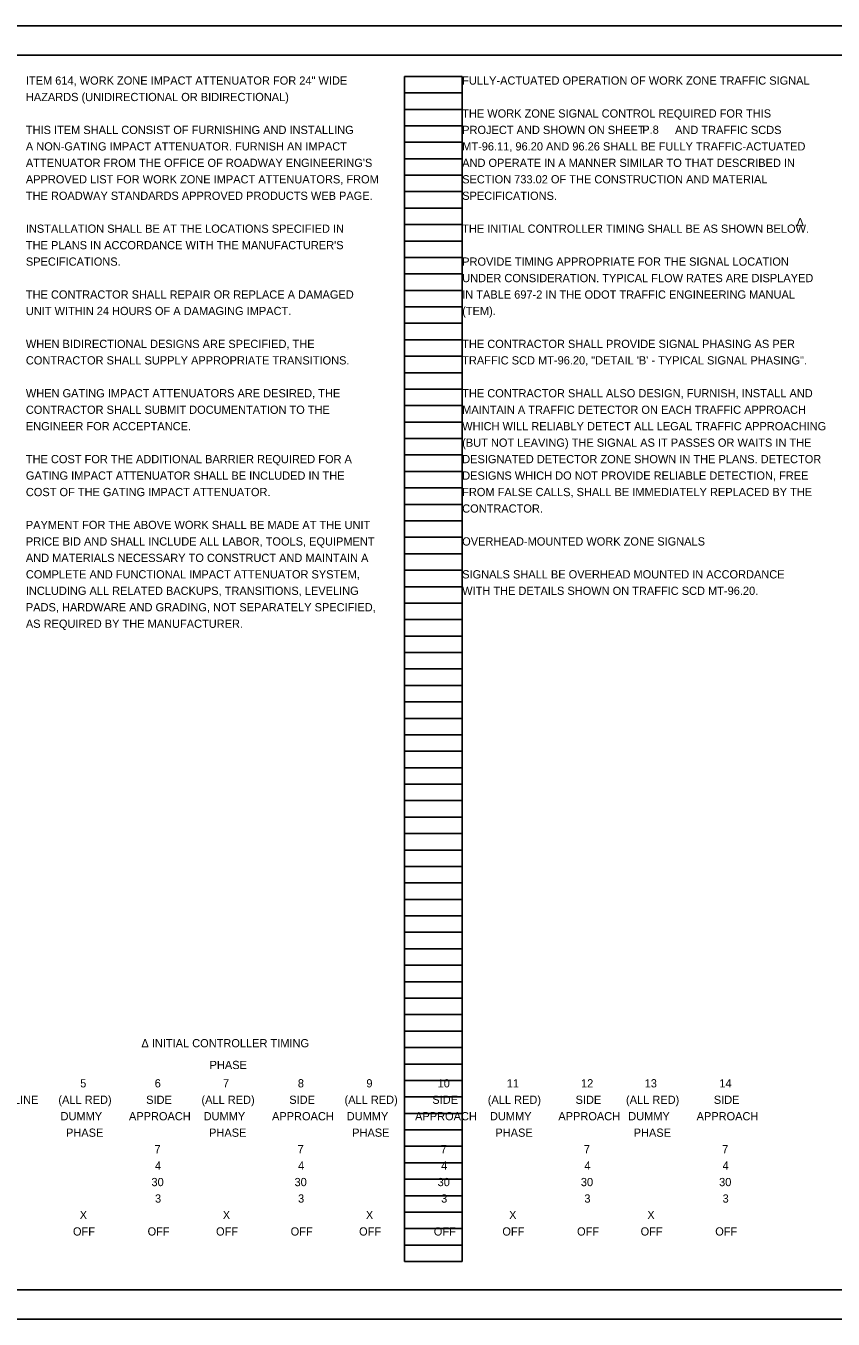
# Model space of a CAD drawing. Extents: x 0 to 40, y 0 to 22.
# Drawn here: x 9.82 to 23.55, y 0 to 22 of the extents above; entities that cross this region are included whole.
import ezdxf

# ---------------------------------------------------------------- set-up
doc = ezdxf.new("R2010")
doc.units = 0
for name, color, linetype in [('SH_Border', 7, 'Continuous'), ('SH_Cut_Line', 7, 'Continuous'), ('SH_Data', 7, 'Continuous'), ('SH_Text', 7, 'Continuous')]:
    doc.layers.add(name, color=color, linetype=linetype)

msp = doc.modelspace()

# ---------------------------------------------------------------- linework, layer by layer
at = {"layer": 'SH_Border'}
msp.add_lwpolyline([(1.5, 21.5), (33.5, 21.5), (33.5, 0.5), (1.5, 0.5)], close=True, dxfattribs=at)
at = {"layer": 'SH_Cut_Line'}
msp.add_lwpolyline([(0, 0), (34, 0), (34, 22), (0, 22)], close=True, dxfattribs=at)
at = {"layer": 'SH_Data'}
for p, q in [((16.26, 0.98), (16.26, 21.14)), ((16.26, 21.14), (17.24, 21.14)), ((17.24, 0.98), (17.24, 21.14)), ((16.26, 20.86), (17.24, 20.86)), ((16.26, 20.58), (17.24, 20.58)), ((16.26, 20.3), (17.24, 20.3)), ((16.26, 20.02), (17.24, 20.02)), ((16.26, 19.74), (17.24, 19.74)), ((16.26, 19.46), (17.24, 19.46)), ((16.26, 19.18), (17.24, 19.18)), ((16.26, 18.9), (17.24, 18.9)), ((16.26, 18.62), (17.24, 18.62)), ((16.26, 18.34), (17.24, 18.34)), ((16.26, 18.06), (17.24, 18.06)), ((16.26, 17.78), (17.24, 17.78)), ((16.26, 17.5), (17.24, 17.5)), ((16.26, 17.22), (17.24, 17.22)), ((16.26, 16.94), (17.24, 16.94)), ((16.26, 16.66), (17.24, 16.66)), ((16.26, 16.38), (17.24, 16.38)), ((16.26, 16.1), (17.24, 16.1)), ((16.26, 15.82), (17.24, 15.82)), ((16.26, 15.54), (17.24, 15.54)), ((16.26, 15.26), (17.24, 15.26)), ((16.26, 14.98), (17.24, 14.98)), ((16.26, 14.7), (17.24, 14.7)), ((16.26, 14.42), (17.24, 14.42)), ((16.26, 14.14), (17.24, 14.14)), ((16.26, 13.86), (17.24, 13.86)), ((16.26, 13.58), (17.24, 13.58)), ((16.26, 13.3), (17.24, 13.3)), ((16.26, 13.02), (17.24, 13.02)), ((16.26, 12.74), (17.24, 12.74)), ((16.26, 12.46), (17.24, 12.46)), ((16.26, 12.18), (17.24, 12.18)), ((16.26, 11.9), (17.24, 11.9)), ((16.26, 11.62), (17.24, 11.62)), ((16.26, 11.34), (17.24, 11.34)), ((16.26, 11.06), (17.24, 11.06)), ((16.26, 10.78), (17.24, 10.78)), ((16.26, 10.5), (17.24, 10.5)), ((16.26, 10.22), (17.24, 10.22)), ((16.26, 9.94), (17.24, 9.94)), ((16.26, 9.66), (17.24, 9.66)), ((16.26, 9.38), (17.24, 9.38)), ((16.26, 9.1), (17.24, 9.1)), ((16.26, 8.82), (17.24, 8.82)), ((16.26, 8.54), (17.24, 8.54)), ((16.26, 8.26), (17.24, 8.26)), ((16.26, 7.98), (17.24, 7.98)), ((16.26, 7.7), (17.24, 7.7)), ((16.26, 7.42), (17.24, 7.42)), ((16.26, 7.14), (17.24, 7.14)), ((16.26, 6.86), (17.24, 6.86)), ((16.26, 6.58), (17.24, 6.58)), ((16.26, 6.3), (17.24, 6.3)), ((16.26, 6.02), (17.24, 6.02)), ((16.26, 5.74), (17.24, 5.74)), ((16.26, 5.46), (17.24, 5.46)), ((16.26, 5.18), (17.24, 5.18)), ((16.26, 4.9), (17.24, 4.9)), ((16.26, 4.62), (17.24, 4.62)), ((16.26, 4.34), (17.24, 4.34)), ((16.26, 4.06), (17.24, 4.06)), ((16.26, 3.78), (17.24, 3.78)), ((16.26, 3.5), (17.24, 3.5)), ((16.26, 3.22), (17.24, 3.22)), ((16.26, 2.94), (17.24, 2.94)), ((16.26, 2.66), (17.24, 2.66)), ((16.26, 2.38), (17.24, 2.38)), ((16.26, 2.1), (17.24, 2.1)), ((16.26, 1.82), (17.24, 1.82)), ((16.26, 1.54), (17.24, 1.54)), ((16.26, 1.26), (17.24, 1.26)), ((16.26, 0.98), (17.24, 0.98))]:
    msp.add_line(p, q, dxfattribs=at)

# ---------------------------------------------------------------- texts
at = {"layer": 'SH_Text'}
for s, p in [('ITEM 614, WORK ZONE IMPACT ATTENUATOR FOR 24" WIDE', (9.82, 21)), ('FULLY-ACTUATED OPERATION OF WORK ZONE TRAFFIC SIGNAL', (17.24, 21)), ('HAZARDS (UNIDIRECTIONAL OR BIDIRECTIONAL)', (9.82, 20.72)), ('THE WORK ZONE SIGNAL CONTROL REQUIRED FOR THIS', (17.24, 20.44)), ('THIS ITEM SHALL CONSIST OF FURNISHING AND INSTALLING', (9.82, 20.16)), ('PROJECT AND SHOWN ON SHEET          AND TRAFFIC SCDS', (17.24, 20.16)), ('P.8', (20.302, 20.164)), ('A NON-GATING IMPACT ATTENUATOR. FURNISH AN IMPACT', (9.82, 19.88)), ('MT-96.11, 96.20 AND 96.26 SHALL BE FULLY TRAFFIC-ACTUATED', (17.24, 19.88)), ("ATTENUATOR FROM THE OFFICE OF ROADWAY ENGINEERING'S", (9.82, 19.6)), ('AND OPERATE IN A MANNER SIMILAR TO THAT DESCRIBED IN', (17.24, 19.6)), ('APPROVED LIST FOR WORK ZONE IMPACT ATTENUATORS, FROM', (9.82, 19.32)), ('SECTION 733.02 OF THE CONSTRUCTION AND MATERIAL', (17.24, 19.32)), ('THE ROADWAY STANDARDS APPROVED PRODUCTS WEB PAGE.', (9.82, 19.04)), ('SPECIFICATIONS.', (17.24, 19.04)), ('Δ', (22.925, 18.593)), ('INSTALLATION SHALL BE AT THE LOCATIONS SPECIFIED IN', (9.82, 18.48)), ('THE INITIAL CONTROLLER TIMING SHALL BE AS SHOWN BELOW.', (17.24, 18.48)), ("THE PLANS IN ACCORDANCE WITH THE MANUFACTURER'S", (9.82, 18.2)), ('SPECIFICATIONS.', (9.82, 17.92)), ('PROVIDE TIMING APPROPRIATE FOR THE SIGNAL LOCATION', (17.24, 17.92)), ('UNDER CONSIDERATION. TYPICAL FLOW RATES ARE DISPLAYED', (17.24, 17.64)), ('THE CONTRACTOR SHALL REPAIR OR REPLACE A DAMAGED', (9.82, 17.36)), ('IN TABLE 697-2 IN THE ODOT TRAFFIC ENGINEERING MANUAL', (17.24, 17.36)), ('UNIT WITHIN 24 HOURS OF A DAMAGING IMPACT.', (9.82, 17.08)), ('(TEM).', (17.24, 17.08)), ('WHEN BIDIRECTIONAL DESIGNS ARE SPECIFIED, THE', (9.82, 16.52)), ('THE CONTRACTOR SHALL PROVIDE SIGNAL PHASING AS PER', (17.24, 16.52)), ('CONTRACTOR SHALL SUPPLY APPROPRIATE TRANSITIONS.', (9.82, 16.24)), ('TRAFFIC SCD MT-96.20, "DETAIL \'B\' - TYPICAL SIGNAL PHASING".', (17.24, 16.24)), ('WHEN GATING IMPACT ATTENUATORS ARE DESIRED, THE', (9.82, 15.68)), ('THE CONTRACTOR SHALL ALSO DESIGN, FURNISH, INSTALL AND', (17.24, 15.68)), ('CONTRACTOR SHALL SUBMIT DOCUMENTATION TO THE', (9.82, 15.4)), ('MAINTAIN A TRAFFIC DETECTOR ON EACH TRAFFIC APPROACH', (17.24, 15.4)), ('ENGINEER FOR ACCEPTANCE.', (9.82, 15.12)), ('WHICH WILL RELIABLY DETECT ALL LEGAL TRAFFIC APPROACHING', (17.24, 15.12)), ('(BUT NOT LEAVING) THE SIGNAL AS IT PASSES OR WAITS IN THE', (17.24, 14.84)), ('THE COST FOR THE ADDITIONAL BARRIER REQUIRED FOR A', (9.82, 14.56)), ('DESIGNATED DETECTOR ZONE SHOWN IN THE PLANS. DETECTOR', (17.24, 14.56)), ('GATING IMPACT ATTENUATOR SHALL BE INCLUDED IN THE', (9.82, 14.28)), ('DESIGNS WHICH DO NOT PROVIDE RELIABLE DETECTION, FREE', (17.24, 14.28)), ('COST OF THE GATING IMPACT ATTENUATOR.', (9.82, 14)), ('FROM FALSE CALLS, SHALL BE IMMEDIATELY REPLACED BY THE', (17.24, 14)), ('CONTRACTOR.', (17.24, 13.72)), ('PAYMENT FOR THE ABOVE WORK SHALL BE MADE AT THE UNIT', (9.82, 13.44)), ('PRICE BID AND SHALL INCLUDE ALL LABOR, TOOLS, EQUIPMENT', (9.82, 13.16)), ('OVERHEAD-MOUNTED WORK ZONE SIGNALS', (17.24, 13.16)), ('AND MATERIALS NECESSARY TO CONSTRUCT AND MAINTAIN A', (9.82, 12.88)), ('COMPLETE AND FUNCTIONAL IMPACT ATTENUATOR SYSTEM,', (9.82, 12.6)), ('SIGNALS SHALL BE OVERHEAD MOUNTED IN ACCORDANCE', (17.24, 12.6)), ('INCLUDING ALL RELATED BACKUPS, TRANSITIONS, LEVELING', (9.82, 12.32)), ('WITH THE DETAILS SHOWN ON TRAFFIC SCD MT-96.20.', (17.24, 12.32)), ('PADS, HARDWARE AND GRADING, NOT SEPARATELY SPECIFIED,', (9.82, 12.04)), ('AS REQUIRED BY THE MANUFACTURER.', (9.82, 11.76)), ('Δ INITIAL CONTROLLER TIMING', (11.785, 4.624)), ('PHASE', (12.944, 4.254)), ('5', (10.744, 3.942)), ('6', (12.011, 3.942)), ('7', (13.172, 3.942)), ('8', (14.445, 3.942)), ('9', (15.61, 3.942)), ('10', (16.822, 3.942)), ('11', (17.998, 3.942)), ('12', (19.261, 3.942)), ('13', (20.343, 3.942)), ('14', (21.613, 3.942)), ('MAINLINE        (ALL RED)      MAINLINE', (6.631, 3.661)), ('(ALL RED)', (10.373, 3.662)), ('SIDE', (11.866, 3.662)), ('(ALL RED)', (12.806, 3.662)), ('SIDE', (14.299, 3.662)), ('(ALL RED)', (15.239, 3.662)), ('SIDE', (16.732, 3.662)), ('(ALL RED)', (17.675, 3.662)), ('SIDE', (19.168, 3.662)), ('(ALL RED)', (20.026, 3.662)), ('SIDE', (21.519, 3.662)), ('DUMMY', (10.41, 3.382)), ('APPROACH', (11.573, 3.382)), ('DUMMY', (12.843, 3.382)), ('APPROACH', (14.006, 3.382)), ('DUMMY', (15.276, 3.382)), ('APPROACH', (16.439, 3.382)), ('DUMMY', (17.712, 3.382)), ('APPROACH', (18.875, 3.382)), ('DUMMY', (20.063, 3.382)), ('APPROACH', (21.226, 3.382)), ('PHASE', (10.503, 3.102)), ('PHASE', (12.936, 3.102)), ('PHASE', (15.369, 3.102)), ('PHASE', (17.805, 3.102)), ('PHASE', (20.156, 3.102)), ('7', (12.008, 2.822)), ('7', (14.441, 2.822)), ('7', (16.874, 2.822)), ('7', (19.31, 2.822)), ('7', (21.661, 2.822)), ('4', (12.016, 2.542)), ('4', (14.449, 2.542)), ('4', (16.882, 2.542)), ('4', (19.318, 2.542)), ('4', (21.668, 2.542)), ('30', (11.956, 2.262)), ('30', (14.389, 2.262)), ('30', (16.822, 2.262)), ('30', (19.258, 2.262)), ('30', (21.609, 2.262)), ('3', (12.016, 1.982)), ('3', (14.449, 1.982)), ('3', (16.882, 1.982)), ('3', (19.318, 1.982)), ('3', (21.668, 1.982)), ('X', (10.736, 1.702)), ('X', (13.169, 1.702)), ('X', (15.602, 1.702)), ('X', (18.038, 1.702)), ('X', (20.388, 1.702)), ('OFF', (10.621, 1.422)), ('OFF', (11.89, 1.422)), ('OFF', (13.054, 1.422)), ('OFF', (14.323, 1.422)), ('OFF', (15.487, 1.422)), ('OFF', (16.757, 1.422)), ('OFF', (17.923, 1.422)), ('OFF', (19.193, 1.422)), ('OFF', (20.274, 1.422)), ('OFF', (21.543, 1.422))]:
    msp.add_text(s, height=0.14, dxfattribs=at).set_placement(p)

doc.saveas('drawing.dxf')
